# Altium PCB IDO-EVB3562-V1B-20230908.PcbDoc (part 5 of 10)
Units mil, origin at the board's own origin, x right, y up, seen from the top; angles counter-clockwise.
Board outline 5314.96 x 3543.31 mil, 4 copper layers (TOP, L2-VCC, L3-GND, BOTTOM), stack 28.8 mil thick; 747 components, 560 nets, 2514 pads, 1964 vias.
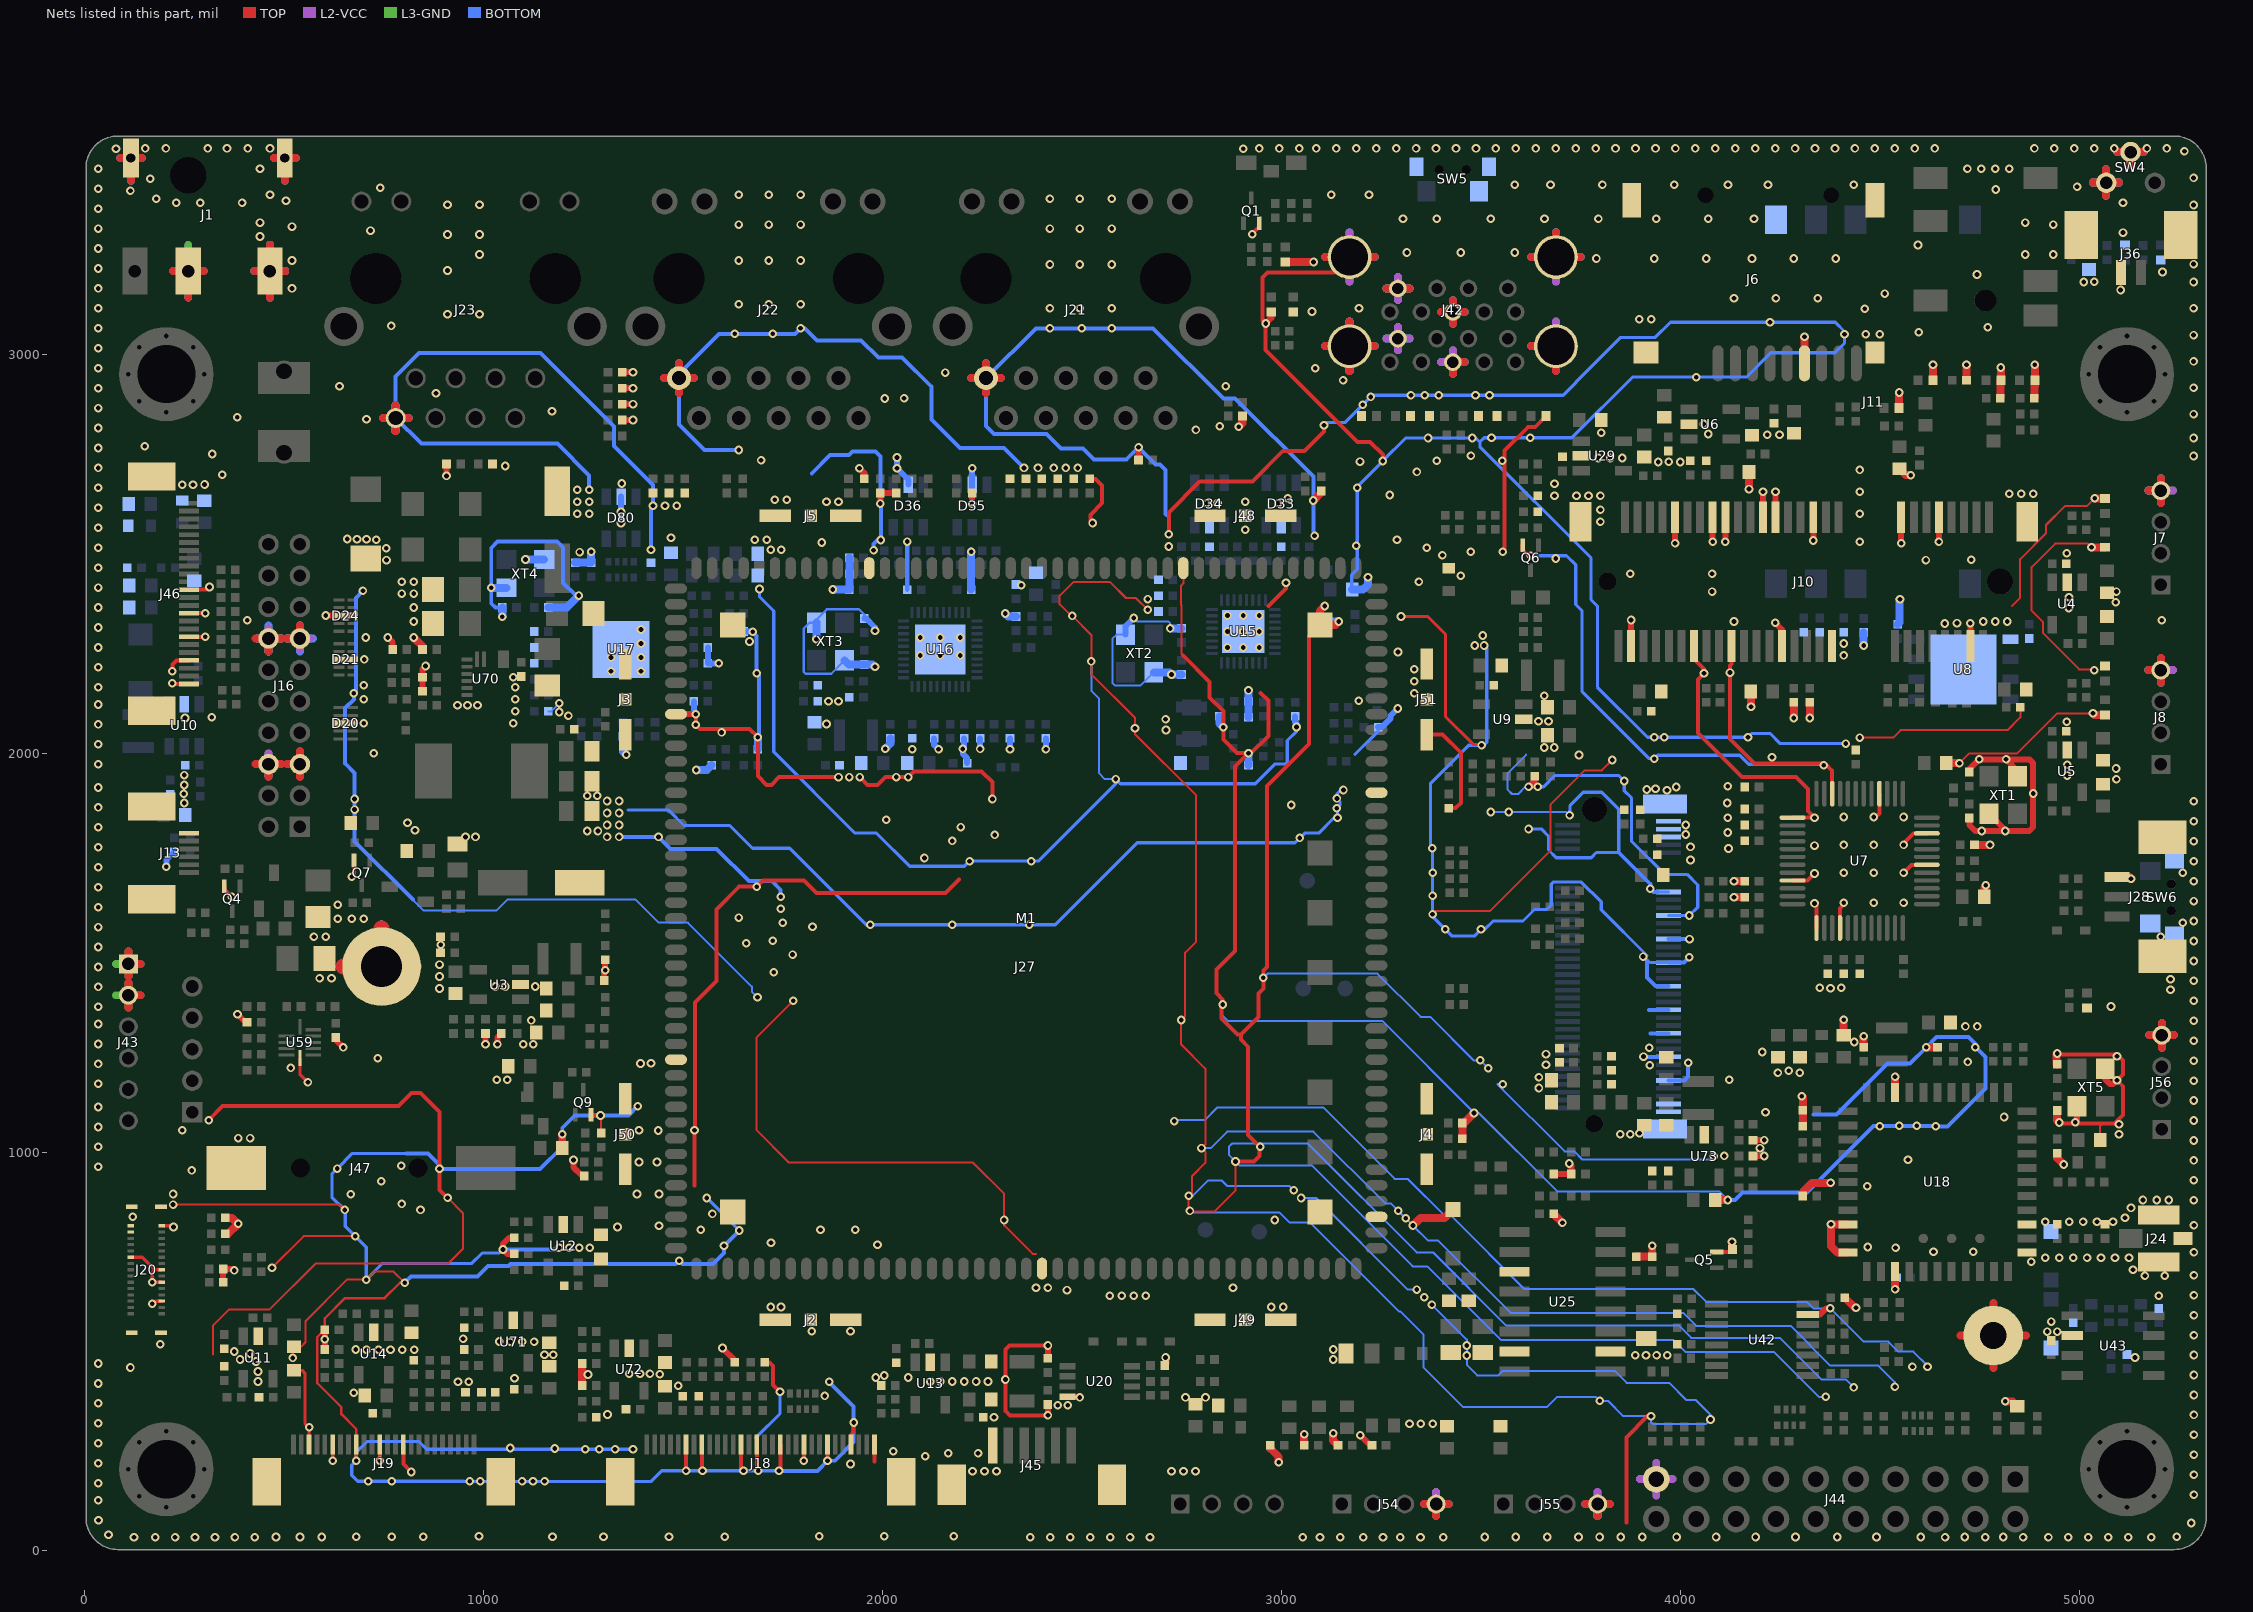
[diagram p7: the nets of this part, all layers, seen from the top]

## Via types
v1: diameter 21.65, hole 11.81, TOP to BOTTOM, 1964 vias

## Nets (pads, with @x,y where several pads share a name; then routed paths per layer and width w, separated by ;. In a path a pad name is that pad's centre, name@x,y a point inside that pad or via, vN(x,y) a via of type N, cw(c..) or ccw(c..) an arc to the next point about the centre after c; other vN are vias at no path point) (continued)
GND: C1.2 C2.1 C3.1 C28.1 C29.1 C30.1 C32.1 C33.1 C34.1 C36.1 C37.1 C39.2 C40.2 C42.2 C43.2 C45.2 C46.2 C53.1 C54.2 C61.1 C62.1 C63.1 C65.1 C67.1 C68.1 C69.1 C70.1 C74.1 C75.1 C76.1 C77.1 C80.1 C81.1 C82.1 C85.1 C86.1 C87.1 C88.1 C89.1 C90.1 C91.1 C92.1 C93.1 C94.1 C95.1 C96.1 C97.1 C98.1 C99.1 C100.1 C101.1 C102.1 C103.1 C104.1 C105.1 C107.1 C108.1 C112.2 C113.2 C114.1 C115.2 C116.2 C126.2 C128.1 C129.1 C130.1 C131.1 C132.1 C133.1 C143.1 C147.1 C150.2 C151.1 C152.1 C155.1 C156.2 C158.1 C159.1 C160.1 C163.1 C164.1 C166.1 C167.1 C168.1 C169.1 C170.1 C171.1 C176.1 C180.1 C189.1 C190.2 C191.1 C207.1 C208.1 C209.1 C210.1 C211.1 C212.1 C213.1 C214.1 C216.2 C217.2 C220.2 C221.2 C223.1 C226.1 C227.1 C261.2 C262.2 C264.1 C265.1 C266.1 C267.1 C268.1 C269.1 C270.1 C271.1 C272.1 C273.1 C274.1 C275.1 C276.1 C277.1 C278.1 C279.1 C280.1 C281.1 C282.1 C283.1 C284.2 C285.1 C287.1 C288.1 C289.1 C291.1 C292.1 C293.1 C294.1 C295.1 C301.1 C302.1 C303.1 C304.1 C305.1 C306.1 C307.2 C308.2 C309.2 C310.1 C311.1 C312.1 C313.1 C314.1 C315.1 C316.1 C318.1 C320.1 C321.1 C322.1 C323.1 C324.1 C325.1 C326.1 C327.1 C328.1 C329.1 C330.1 C331.1 C332.1 C333.1 C334.1 C335.1 C336.1 C337.1 C338.1 C339.1 C340.1 C341.1 C342.1 C343.1 C344.1 C347.1 C348.1 C349.1 C350.1 C351.1 C352.1 C355.1 C356.1 C357.1 C358.1 C359.1 C360.1 C361.1 C362.1 C363.1 C364.1 C365.1 C366.1 C367.1 C368.1 C528.2 C530.2 C531.2 C532.2 C533.2 C806.2 C807.1 C808.1 C809.1 C811.2 C812.2 C813.2 C814.2 C870.2 C871.2 C1010.1 C1011.1 C1013.1 C1014.1 C1015.1 C1016.1 C1017.1 C1018.1 C1019.1 C1020.1 C1022.1 C1023.1 C1024.1 C1025.1 C1026.1 C1027.1 C1028.1 C1029.1 C1030.1 C1031.1 C1032.1 C1033.1 C1035.1 C1036.1 C1037.1 C1038.1 C1040.1 C1041.1 C1042.1 C1044.1 C1045.1 C1046.1 C1047.1 D3.A D4.1 D5.2 D6.1 D7.2 D8.1 D9.2 D20.3 D20.8 D21.3 D21.8 D24.3 D24.8 D33.2 D34.2 D35.2 D36.2 D37.1 D38.1 D39.1 D40.1 D41.1 D42.1 D46.2 D50.2 D51.2 D65.2 D66.2 D67.2 D68.2 D69.2 D79.C D80.2 D194.C D195.C J1.2 J1.3 J1.5 J1.6 J2.1 J2.2 J2.3 J3.1 J3.2 J3.3 J4.1 J4.2 J4.3 J5.1 J5.2 J5.3 J6.6 J6.10 J6.11 J6.12 J6.13 J7.4 J8.4 J10.4 J10.9 J10.15 J10.18 J10.21 J10.26 J10.27 J10.29 J10.34 J10.35 J10.37 J10.40 J10.43 J10.50 J10.55 J10.56 J11.C5 J13.6 J13.7 J13.8 J16.5 J16.6 J16.13 J16.14 J18.1 J18.4 J18.7 J18.10 J18.13 J18.16 J18.18 J18.23 J18.25 J18.31 J18.32 J19.10 J19.13 J19.16 J19.19 J19.22 J19.25 J19.26 J20.6 J20.12 J20.16 J20.19 J20.27 J20.29 J20.30 J20.31 J20.32 J20.33 J20.34 J21.10 J22.10 J23.8 J24.1 J24.3 J24.4 J27.1 J27.3 J27.9 J27.15 J27.21 J27.27 J27.33 J27.39 J27.45 J27.51 J27.57 J27.71 J27.73 J27.75 J27.G1 J27.G2 J27.G3 J27.G4 J28.3 J28.4 J28.5 J36.2 J36.3 J36.4 J42.4 J42.7 J42.13 J42.16 J42.19 J42.20 J42.21 J42.22 J43.1 J43.2 J44.19 J45.6 J45.7 J45.8 J46.1 J46.4 J46.7 J46.10 J46.13 J46.25 J46.26 J47.2 J48.1 J48.2 J48.3 J49.1 J49.2 J49.3 J50.1 J50.2 J50.3 J51.1 J51.2 J51.3 J54.4 J55.4 J56.4 M1.3 M1.30 M1.55 M1.75 M1.95 M1.117 M1.152 M1.173 M1.180 M1.181 M1.182 M6.1 Q1.2 Q4.2 Q5.2 Q6.2 Q7.2 Q9.2 R10.1 R31.2 R34.2 R35.2 R47.2 R82.1 R133.1 R135.1 R137.1 R139.1 R158.1 R171.1 R174.1 R176.1 R179.1 R180.1 R181.1 R183.1 R184.1 R187.1 R193.2 R200.1 R209.2 R211.2 R216.2 R218.1 R220.2 R239.1 R244.1 R253.1 R306.2 R316.1 R341.2 R389.1 R412.1 R413.1 R414.2 R442.1 R446.2 R447.1 R459.2 R782.1 R785.1 R1060.2 R1067.1 R1070.1 R1169.1 R1177.2 R1178.2 R1192.2 R1198.1 R1202.2 SW4.2 SW4.3 SW5.1 SW5.2 SW5.3 SW6.1 SW6.2 SW6.3 U3.2 U4.2 U5.2 U6.2 U7.6 U7.10 U7.16 U7.22 U7.25 U7.33 U7.37 U7.40 U8.1 U8.9 U9.2 U10.2 U11.2 U12.2 U13.2 U14.2 U15.33 U16.41 U17.33 U18.1 U18.3 U18.20 U18.31 U18.33 U18.36 U20.4 U25.2 U25.11 U25.15 U29.2 U42.15 U43.2 U59.6 U70.1 U70.3 U71.2 U72.2 U73.2 XT1.2 XT1.4 XT2.2 XT2.4 XT3.2 XT3.4 XT4.2 XT4.4 XT5.2 XT5.4 | length 88813
  TOP w5: v1(222.01,868.3) 638.66,868.3 v1(651.98,854.98) ; 321.53,492.47 321.53,564.47 362.52,605.46 463.89,605.46 578.93,720.5 911.1,720.5 948.75,758.15 948.75,846.53 v1(910.14,885.14) ; v1(470,710) 549.07,789.07 v1(678.44,789.07) ; C97.1@525,512.44 543.37,512.44 553.93,523 553.93,576.39 657.54,680 v1(706,680) 726.5,700.5 774.5,700.5 v1(802.5,672.5) ; v1(1293.34,1091.67) 1295,1090.01 R1192.2@1295,1047.72 ; v1(1776.48,1379.48) 1684.82,1287.82 1684.82,1054.7 1765.64,973.89 2227.11,973.89 2305.18,895.82 v1(2305.18,829.77) 2305.18,816.4 2376.58,745 2385,745 ; v1(2665,2359.59) 2635.59,2389 2610.72,2389 2571,2428.72 2478.72,2428.72 2444.67,2394.67 2444.67,2373.13 2473.76,2344.04 v1(2475.84,2344.04) 2523.67,2296.21 v1(2523.67,2230) 2523.67,2198.18 2633.33,2088.52 v1(2633.33,2062.6) 2633.33,2047.43 2786.65,1894.11 2786.65,1527.65 2759,1500 2759,1341 v1(2749,1331) 2749,1269.7 2809.55,1209.15 2809.55,1019.55 v1(2800,1010) 2809.55,1000.45 2809.55,972.84 2776.68,939.96 2776.68,898.46 v1(2768.35,890.14) 2767.49,889.27 2767.49,855.93 v1(2770.96,852.46) 2771.97,851.45 2833.45,851.45 2885.12,903.12 v1(2885.12,976.47) ; 2753.39,2245.39 2750,2248.79 2750,2371 2749.17,2371.83 2749.17,2420.17 2754.53,2425.53 M1.55@2754.53,2463.78 ; v1(3379.33,1596.27) 3387.66,1604.59 3523.85,1604.59 3674.43,1755.17 3674.43,1871.16 3760.26,1957 3803.55,1957 v1(3829.43,1982.89) ; v1(4450,2039) 4534,2039 4552.57,2057.57 4820.51,2057.57 4852.72,2089.78 C313.1@4852.72,2114.99 ; v1(4700,1975) 4724.57,1999.57 4844.54,1999.57 4944.97,2100 v1(5035,2100) ; 4832,2369 4852.1,2389.1 4852.1,2486.1 4917,2551 4917,2572 4965,2620 5020.2,2620 v1(5039.1,2638.9) ; v1(5031,2516.1) 5022.1,2525 4940,2525 4881.1,2466.1 4881.1,2357.41 4909.81,2328.7 4909.81,2300.57 5000.38,2210 5036,2210 v1(5038,2208) ; C176.1@5052.56,1030 5052.56,1064.56 5060,1072
  TOP w6: J19.16@681.1,267.01 681.1,305.9 643.93,343.07 643.93,360.33 583.43,420.84 583.43,536.15 C268.1@602.28,555 602.28,583.02 653.26,634 752.11,634 790.61,672.5 v1(802.5,672.5)
  TOP w8: J20.19@116.03,736.49 144.96,736.49 176.45,705 ; v1(169.96,619.93) 176.29,626.26 J20.6@193.98,626.26 ; J20.12@193.98,673.5 v1(169.88,673.5) 169.88,698.43 176.45,705 ; J20.16@193.98,705 176.45,705 ; J20.30@193.98,815.23 219.77,815.23 v1(223,812) ; C96.1@525,452.56 545.44,452.56 552.43,445.57 552.43,320.56 v1(562.99,310) J19.22@562.99,267.01 ; U59.6@540,1235.63 540,1195 v1(560,1175) ; v1(622.05,226.18) J19.19@622.05,267.01 ; v1(681.1,226.18) J19.16@681.1,267.01 ; J18.4@1921.38,267.01 1921.38,292.38 1928,299 v1(1928,322) ; v1(3300,2342.48) 3367.52,2342.48 3411.75,2298.25 3411.75,2091.51 3481.19,2022.06 3500.03,2022.06 v1(3502.13,2019.96)
  TOP w10: v1(220,2175) 221.38,2173.62 J46.1@262.01,2173.62 ; v1(220,2205) 220,2222.68 230,2232.68 J46.4@262.01,2232.68 ; J46.7@262.01,2291.73 v1(302.83,2291.73) ; J46.10@262.01,2350.79 v1(302.83,2350.79) ; J46.13@262.01,2409.84 306.65,2409.84 v1(313.35,2416.54) ; v1(311.42,1080) 346.42,1115 787,1115 820,1148 842,1148 890,1100 v1(890,957.83) 890,905.28 v1(910.14,885.14) ; Q4.2@350.31,1666.5 350.31,1658.36 v1(368.68,1640) ; v1(670,1690) 675.32,1695.32 Q7.2@675.32,1731.5 ; v1(740.16,226.18) J19.13@740.16,267.01 ; J19.10@799.21,267.01 799.21,217.79 v1(819,198) ; Q9.2@1269.68,1093.5 1291.51,1093.5 v1(1293.34,1091.67) ; v1(1508,201) J18.25@1507.99,267.01 ; 1529,916 v1(1529,1055) 1530.43,1056.44 1530.43,1375.43 1583.79,1428.79 1583.79,1608.32 1640.6,1665.12 v1(1685,1665.12) 1700.73,1680.85 1803.15,1680.85 1835,1649 2158,1649 2192,1683 ; v1(1532.36,2097.64) v1(1532.36,2070.98) 1542.51,2060.83 1666.89,2060.83 v1(1687.72,2040) 1687.72,1942.39 1709.77,1920.33 1721.77,1920.33 1741.44,1940 v1(1890,1940) ; J18.23@1547.36,267.01 1547.36,202.64 v1(1549,201) ; J18.18@1645.79,267.01 1645.79,207.21 v1(1652,201) ; J18.16@1685.16,267.01 1685.16,204.84 v1(1689,201) ; R1178.2@1705,472.72 1717.28,472.72 1726.3,463.7 1726.3,416.31 v1(1743.44,399.16) ; v1(1741,201) 1744.21,204.21 J18.13@1744.21,267.01 ; v1(1803.27,226.18) J18.10@1803.27,267.01 ; v1(1862.32,226.18) J18.7@1862.32,267.01 ; v1(1943.31,1940) 1962.98,1920.33 1987.9,1920.33 2007.57,1940 v1(2035,1940) v1(2065,1940) 2079.17,1954.17 2248.86,1954.17 2275.91,1927.12 v1(2275.91,1885.03) ; 1980.43,224.57 J18.1@1980.43,267.01 ; v1(2415,340) 2320,340 2308.5,351.5 v1(2308.5,430) 2308.5,505 2318.5,515 v1(2415,515) ; C272.1@2520,2687.72 2534.28,2687.72 2551,2671 2551,2626.55 2521.42,2596.97 2521.42,2582.58 v1(2527,2577) ; v1(2718,2549) 2718,2603.27 2795.56,2680.83 2927.58,2680.83 3003.75,2757 3058,2757 3107,2806 v1(3107,2822.35) ; 2753.39,2245.39 2820.61,2178.18 2820.61,2139.39 2854.69,2105.31 v1(2854.69,2065) 2854.69,2034.1 2888.79,2000 v1(2917.72,2000) ; v1(2885.12,976.47) 2931.47,976.47 2945,990 2945,1011 v1(2947,1013) 2917,1043 2917,1264 2899,1282 2899,1295 ; v1(2927,3301) 2944.68,3318.68 Q1.2@2944.68,3328.5 ; 2948,2151 2967.48,2131.52 2967.48,2043.03 2924.45,2000 v1(2917.72,2000) ; 2967.48,2368.62 3011.79,2412.93 v1(3011.79,2426.82) ; M1.180@3096.65,2321.65 3069.14,2294.14 3069.14,2022.96 2964.15,1917.98 2964.15,1464.03 2955,1454.87 v1(2955,1436.67) 2955.83,1435.85 2955.83,1410.42 2942.5,1397.09 2942.5,1338.5 2899,1295 ; J42.21@3171.34,3243.74 3132.6,3205 2965,3205 2952.8,3192.8 2952.8,3084.96 v1(2960.75,3077) 2960.75,3010.68 3191.59,2779.85 3222.88,2779.85 3254.5,2748.23 v1(3254.5,2732.5) ; J51.2@3365,2046.42 3404.58,2046.42 3450,2001 3450,1875 3437.28,1862.28 C271.1@3419.99,1862.28 ; v1(3555,2505) 3560,2510 3560,2758.67 3618.33,2817 3635.9,2817 D39.1@3663.9,2845 ; Q6.2@3605.32,2521.5 3605.32,2509.68 3620,2495 v1(3625,2495) ; 3865,71 3865,284.43 3918.6,338.02 v1(3926.84,338.02) ; J10.40@4034.4,2268.6 4034.4,2235.95 4059.82,2210.53 v1(4059.82,2200.01) 4044.15,2184.34 4044.15,2050.85 4155,1940 4290,1940 4320,1910 4320,1855 v1(4336.7,1838.3) U7.25@4281.7,1838.3 ; Q5.2@4091.5,749.68 4124.97,749.68 R446.2@4131,755.72 ; J10.34@4128.9,2268.6 4128.9,2223.9 4125,2220 v1(4125,2202) 4125,2035 4186,1974 4356,1974 v1(4360,1970) 4367,1970 4381.1,1955.9 U7.22@4381.1,1898.3 ; U7.33@4281.7,1680.8 4319.2,1680.8 v1(4336.7,1698.3) ; v1(4336.7,1623.3) 4341.7,1618.3 U7.37@4341.7,1561.7 ; U7.40@4400.8,1561.7 4400.8,1610.8 4410,1620 v1(4410,1625) ; v1(4485,1840) 4490,1840 4499.2,1849.2 U7.16@4499.2,1898.3 ; v1(4560,1700) 4580.2,1720.2 U7.6@4618.3,1720.2 ; v1(4560,1770) 4560,1773.9 4585,1798.9 U7.10@4618.3,1798.9 ; v1(4945,1247) 4947.12,1244.88 5094.41,1244.88 5110,1229.29 5110,1195 v1(5095,1180) 5110,1165 5110,1093 5089,1072 5060,1072 4995,1072 4952,1072 v1(4950,1074) ; 2899,1295 2890,1295 2850.32,1334.67 2850.32,1367.21 v1(2853.11,1370) 2853.11,1382.56 2837.3,1398.37 2837.3,1457.21 2884.15,1504.06 2884.15,1966.43 v1(2917.72,2000)
  TOP w15: C1028.1@347.72,673.99 C288.1@347.72,707 371.36,707 v1(375,703.36) ; v1(383.36,1345.22) 403.58,1325 C285.1@407.28,1325 ; R139.1@602.28,505 v1(602.28,530.72) C268.1@602.28,555 ; v1(605,2345) D24.3@639.44,2345 D24.8@670.56,2345 ; C284.2@630.01,1287.28 630.01,1280.89 v1(648.56,1262.34) ; v1(760,2290) 772.28,2277.72 R1060.2@772.28,2260 ; R782.1@847.28,2155 R785.1@847.28,2190 847.28,2210.6 v1(855,2218.32) ; v1(907.28,2695) C166.1@907.28,2725 ; v1(1005,1270) R10.1@1005,1297.28 ; v1(1035,1270) 1035,1287.28 C37.1@1045,1297.28 ; R135.1@1077.28,745 1059.91,745 v1(1049,755.91) 1049,770 1064,785 C266.1@1077.28,785 ; v1(1225.6,980) 1225.6,962.3 1247.89,940.01 C269.1@1252.28,940.01 ; C36.1@1302.72,1429.99 1302.72,1453.33 v1(1304.99,1455.6) C95.1@1304.99,1482.28 ; C152.1@1347.72,2834.99 v1(1375,2834.99) ; R200.1@1347.72,2875 v1(1375,2875) ; C150.2@1347.72,2915.01 v1(1375,2915.01) ; R218.1@1347.72,2955 v1(1375,2955) ; M1.95@1482.87,2097.64 v1(1532.36,2097.64) ; v1(1599.33,508.67) 1630.01,477.99 C94.1@1630.01,472.72 ; v1(1942.48,2714.31) 1955,2701.8 C270.1@1955,2687.72 ; v1(1994.99,2625.6) C147.1@1994.99,2652.28 C131.1@2035,2652.28 ; v1(2225,2625.6) C112.2@2225,2652.28 ; v1(2415,340) C191.1@2415,367.28 ; C189.1@2415,482.72 v1(2415,515) ; U20.4@2464.29,386.62 2493.38,386.62 v1(2495,385) ; C114.1@2642.28,2735.01 v1(2642.28,2766.68) ; C190.2@2707.72,465.01 2712.72,470.01 2712.72,482.28 v1(2710,485) ; v1(2960.75,3077) 2975,3091.25 D37.1@2975,3106.1 ; v1(3198.3,289.92) 3223.22,265 C217.2@3227.28,265 ; v1(3620,1915.6) 3635,1930.6 R442.1@3635,1942.28 ; R306.2@3682.72,945 C214.1@3727.28,945.01 3727.28,966.02 v1(3721.84,971.47) ; J10.50@3876.9,2268.6 v1(3876.9,2333.8) ; v1(3987.2,2526.2) J10.43@3987.2,2591.4 ; v1(4081.6,2530.2) J10.37@4081.6,2591.4 ; v1(4113.2,2530.2) J10.35@4113.2,2591.4 ; R1169.1@4182.72,990 v1(4211,990) ; C1045.1@4182.72,1030 v1(4211,1030) ; J10.29@4207.6,2591.4 v1(4207.6,2655) ; v1(4238,2327) 4254.9,2310.1 J10.26@4254.9,2268.6 ; J10.27@4239.1,2591.4 v1(4239.1,2655) ; U42.15@4319.7,593.14 4351.14,593.14 4366.31,608.32 v1(4376.35,608.32) ; v1(4333.6,2533) J10.21@4333.6,2591.4 ; v1(4554.1,2526.2) J10.15@4554.1,2591.4 ; v1(4648.6,2530) J10.9@4648.6,2591.4 ; C53.1@4725,1837.28 4725,1820 4740,1805 v1(4756,1805) v1(4815,1805) ; C54.2@4725,1952.72 4725,1959.57 v1(4750,1984.57) v1(4817,1984.57) ; J10.4@4727.3,2268.6 v1(4727.3,2325.8) ; XT1.4@4774.57,1847.76 4815,1807.32 v1(4815,1805) ; XT1.2@4845.43,1942.24 4845.43,1956.13 v1(4817,1984.57) ; XT5.2@4994.57,1114.76 4994.57,1072.43 v1@4995,1072 ; XT5.4@5065.43,1209.24 5065.43,1182.57 5078,1170 5085,1170 v1(5095,1180) ; v1(4815,1805) 4875,1805 4885,1815 v1(4885,1899) 4885,1975 4875.43,1984.57 v1(4817,1984.57)
  TOP w20: 89.61,3491.9 J1.6@116.3,3491.9 ; 110,1362.49 J43.2@110,1393.11 ; 110,1423.73 J43.2@110,1393.11 ; 110,1441.23 J43.1@110,1471.85 ; 110,1502.47 J43.1@110,1471.85 ; 116.3,3435.69 J1.6@116.3,3491.9 ; 140.62,1393.11 J43.2@110,1393.11 ; 140.62,1471.85 J43.1@110,1471.85 ; 142.99,3491.9 J1.6@116.3,3491.9 ; 221.5,3208.4 J1.3@260,3208.4 ; 260,3142.34 J1.3@260,3208.4 ; 298.5,3208.4 J1.3@260,3208.4 ; C1030.1@352.72,794.99 359.99,794.99 v1(385,820) 370.01,834.99 C1029.1@352.72,834.99 ; 426.2,3208.4 J1.2@464.7,3208.4 ; 428.67,1972.48 J16.6@461.26,1972.48 ; 428.67,2287.44 J16.14@461.26,2287.44 ; 461.26,1939.89 J16.6@461.26,1972.48 ; 461.26,2254.85 J16.14@461.26,2287.44 ; 464.7,3142.34 J1.2@464.7,3208.4 ; 464.7,3274.46 J1.2@464.7,3208.4 ; 475.41,3491.9 J1.5@502.1,3491.9 ; 493.85,1972.48 J16.6@461.26,1972.48 ; 493.85,2287.44 J16.14@461.26,2287.44 ; 502.1,3435.69 J1.5@502.1,3491.9 ; 503.2,3208.4 J1.2@464.7,3208.4 ; 507.41,1972.48 J16.5@540,1972.48 ; 507.41,2287.44 J16.13@540,2287.44 540,2320.03 ; 528.78,3491.9 J1.5@502.1,3491.9 ; 540,1939.89 J16.5@540,1972.48 ; 540,2005.07 J16.5@540,1972.48 ; 748,2840 J23.8@780,2840 ; 780,2808 J23.8@780,2840 ; 780,2872 J23.8@780,2840 ; 812,2840 J23.8@780,2840 ; v1(825,2290) 847.28,2267.72 C814.2@847.28,2260 ; C1033.1@1197.56,1010 v1(1197.56,1045) ; R1070.1@1247.28,415 1247.28,441.28 1248.28,442.28 ; C1018.1@1247.28,470 1247.28,443.28 1248.28,442.28 ; v1(1262.28,442.28) 1248.28,442.28 ; 1453,2940 J22.10@1490,2940 ; 1490,2903 J22.10@1490,2940 ; 1490,2977 J22.10@1490,2940 ; 1527,2940 J22.10@1490,2940 ; 2223,2940 J21.10@2260,2940 ; 2260,2903 J21.10@2260,2940 ; 2260,2977 J21.10@2260,2940 ; 2297,2940 J21.10@2260,2940 ; v1(2893.2,2818.33) 2902.72,2827.85 C113.2@2902.72,2845.01 ; C221.2@2972.28,265 2972.28,257.38 2993.53,236.12 v1(2993.53,222.17) ; D46.2@3010,3231.1 v1(3081,3231.1) ; C220.2@3057.28,265 v1(3057.28,292.28) ; v1(3080.48,2633.19) 3100,2652.71 C279.1@3100,2657.28 ; v1(3108.78,2368.98) 3096.65,2356.85 M1.180@3096.65,2321.65 3135.63,2321.65 v1(3143.98,2330) ; 3109.34,3020.12 J42.20@3171.34,3020.12 ; 3109.34,3243.74 J42.21@3171.34,3243.74 3233.34,3243.74 ; v1(3130,295) 3130,277.28 C216.2@3142.28,265 ; 3171.34,2958.12 J42.20@3171.34,3020.12 ; 3171.34,3082.12 J42.20@3171.34,3020.12 ; 3233.34,3020.12 J42.20@3171.34,3020.12 ; 3263.2,3165 J42.4@3292.2,3165 3321.2,3165 ; v1(3329.96,815.96) 3348.86,834.86 3408.84,834.86 D79.C@3430,856.02 ; 3357.49,117.72 J54.4@3388.11,117.72 ; 3388.11,87.09 J54.4@3388.11,117.72 ; 3401,3105.94 J42.7@3430,3105.94 ; 3418.73,117.72 J54.4@3388.11,117.72 ; 3430,2950.96 J42.16@3430,2979.96 3459,2979.96 ; 3430,3076.94 J42.7@3430,3105.94 ; 3430,3134.94 J42.7@3430,3105.94 ; C302.1@3453.72,1033 R389.1@3453.72,1073 3458.18,1073 v1(3483.18,1098) ; 3459,3105.94 J42.7@3430,3105.94 ; 3626.66,3020.12 J42.19@3688.66,3020.12 3688.66,2958.12 ; 3626.66,3243.74 J42.22@3688.66,3243.74 ; C209.1@3682.72,844.99 v1(3704.76,822.95) ; 3688.66,3305.74 J42.22@3688.66,3243.74 ; 3750.66,3243.74 J42.22@3688.66,3243.74 ; 3762.49,117.72 J55.4@3793.11,117.72 ; 3793.11,87.09 J55.4@3793.11,117.72 ; 3823.73,117.72 J55.4@3793.11,117.72 ; C208.1@3890,737.71 C207.1@3930,737.72 v1(3930,765) ; C1037.1@4087.56,880 v1(4119.14,880) ; v1(4130,775) 4130,756.72 R446.2@4131,755.72 ; v1(4135,1639) C311.1@4162.28,1639 ; v1(4135,1679) C306.1@4162.28,1679 ; v1(4172.56,2662) C67.1@4172.56,2705 ; v1(4177.44,2116) C69.1@4177.44,2155 ; v1(4285,2088.28) C76.1@4285,2127.28 ; v1(4305,1140) 4307.28,1137.72 C343.1@4307.28,1105 C180.1@4307.28,1065 ; R244.1@4307.28,890 4307.28,900.28 4330,923 v1(4377,923) ; J6.6@4311.54,2977.13 v1(4311.54,3043.54) ; v1(4325,2088.28) C1035.1@4325,2127.28 ; v1(4378,818.7) 4377.97,764.03 4394.17,747.83 U18.33@4420.59,747.83 ; v1(4378,818.7) U18.31@4420.59,818.7 ; C366.1@4410,1292.56 v1(4410,1332) ; C1036.1@4412.72,634.99 4437.71,610 v1(4440.65,610) ; C342.1@4460,1262.72 v1(4460,1290) ; v1(4538.7,656.3) U18.36@4538.7,700.59 ; U18.20@4538.7,1149.41 v1(4538.7,1189) ; D69.2@4548.9,2865 v1(4548.9,2904) ; C280.1@4550,2712.44 4565.44,2697 v1(4578,2697) ; v1(4617,1262.72) C170.1@4645,1262.72 ; D68.2@4633.9,2935 v1(4633.9,2974) ; C356.1@4666.56,1975 v1(4700,1975) ; 4703.19,540 M6.1@4785,540 ; R316.1@4717.72,2935 v1(4717.72,2974) ; C303.1@4737.72,1770 v1(4776.72,1770) ; C355.1@4762.56,1640 4762.56,1661.56 4766,1665 4766,1666 4766.79,1666.79 4766.79,1668.21 v1(4766,1669) ; 4785,458.19 M6.1@4785,540 ; 4785,621.8 M6.1@4785,540 ; R447.1@4802.72,2890 4802.72,2933.82 D66.2@4803.9,2935 v1(4803.9,2966.9) ; v1(4815,375) 4832.56,375 C264.1@4845,362.56 ; 4866.81,540 M6.1@4785,540 ; C223.1@4887.72,2890 4887.72,2918.72 4888.9,2919.9 D67.2@4888.9,2935 v1(4888.9,2974) ; C344.1@4945,997.28 4945,985.47 v1(4961.47,969) ; C167.1@4945,1104.28 4945,1079 v1(4950,1074) ; C171.1@4945,1219.72 4943.59,1221.13 4943.59,1245.59 v1(4945,1247) ; v1(5031,2516.1) D4.1@5065,2516.1 ; v1(5035,2100) 5038.9,2096.1 D6.1@5065,2096.1 ; 5035.36,3430 SW4.2@5067.95,3430 ; v1(5039.1,2638.9) D5.2@5065,2638.9 ; 5067.95,3397.41 SW4.2@5067.95,3430 ; 5067.95,3462.59 SW4.2@5067.95,3430 ; J28.3@5095,1689.21 5125.79,1689.21 v1(5130,1685) ; 5096.38,3506.77 SW4.3@5128.98,3506.77 ; 5100.55,3430 SW4.2@5067.95,3430 ; 5128.98,3474.18 SW4.3@5128.98,3506.77 ; 5161.57,3506.77 SW4.3@5128.98,3506.77 ; 5174.38,2208.11 J8.4@5205,2208.11 ; 5174.38,2658.11 J7.4@5205,2658.11 ; 5176.66,1293.11 J56.4@5207.28,1293.11 ; 5205,2177.49 J8.4@5205,2208.11 ; 5205,2238.73 J8.4@5205,2208.11 ; 5205,2627.49 J7.4@5205,2658.11 ; 5205,2688.73 J7.4@5205,2658.11 ; 5207.28,1262.49 J56.4@5207.28,1293.11 ; 5207.28,1323.73 J56.4@5207.28,1293.11 ; 5237.91,1293.11 J56.4@5207.28,1293.11
  TOP w40: J27.G3@649.1,1465 J27.G4@744.68,1465 J27.G3@744.68,1560.59
  L2-VCC w20: 89.61,3491.9 J1.6@116.3,3491.9 ; 116.3,3435.69 J1.6@116.3,3491.9 ; 142.99,3491.9 J1.6@116.3,3491.9 ; 426.2,3208.4 J1.2@464.7,3208.4 ; 434.57,1972.48 J16.6@461.26,1972.48 ; 434.57,2287.44 J16.14@461.26,2287.44 ; 461.26,1945.79 J16.6@461.26,1972.48 ; 461.26,1999.17 J16.6@461.26,1972.48 ; 461.26,2260.75 J16.14@461.26,2287.44 ; 461.26,2314.13 J16.14@461.26,2287.44 ; 464.7,3142.34 J1.2@464.7,3208.4 ; 464.7,3274.46 J1.2@464.7,3208.4 ; 475.41,3491.9 J1.5@502.1,3491.9 ; 487.95,1972.48 J16.6@461.26,1972.48 ; 487.95,2287.44 J16.14@461.26,2287.44 ; 502.1,3435.69 J1.5@502.1,3491.9 ; 503.2,3208.4 J1.2@464.7,3208.4 ; 513.31,1972.48 J16.5@540,1972.48 ; 513.31,2287.44 J16.13@540,2287.44 ; 528.78,3491.9 J1.5@502.1,3491.9 ; 540,1945.79 J16.5@540,1972.48 ; 540,1999.17 J16.5@540,1972.48 ; 540,2260.75 J16.13@540,2287.44 ; 540,2314.13 J16.13@540,2287.44 ; 566.69,2287.44 J16.13@540,2287.44 ; 748,2840 J23.8@780,2840 ; 780,2808 J23.8@780,2840 ; 780,2872 J23.8@780,2840 ; 812,2840 J23.8@780,2840 ; 1453,2940 J22.10@1490,2940 ; 1490,2903 J22.10@1490,2940 ; 1490,2977 J22.10@1490,2940 ; 1527,2940 J22.10@1490,2940 ; 2223,2940 J21.10@2260,2940 ; 2260,2903 J21.10@2260,2940 ; 2260,2977 J21.10@2260,2940 ; 2297,2940 J21.10@2260,2940 ; 3109.34,3020.12 J42.20@3171.34,3020.12 ; 3109.34,3243.74 J42.21@3171.34,3243.74 ; 3171.34,2958.12 J42.20@3171.34,3020.12 ; 3171.34,3082.12 J42.20@3171.34,3020.12 ; 3171.34,3181.74 J42.21@3171.34,3243.74 ; 3171.34,3305.74 J42.21@3171.34,3243.74 ; 3233.34,3020.12 J42.20@3171.34,3020.12 ; 3233.34,3243.74 J42.21@3171.34,3243.74 ; 3263.2,3039.02 J42.13@3292.2,3039.02 ; 3263.2,3165 J42.4@3292.2,3165 ; 3292.2,3010.02 J42.13@3292.2,3039.02 ; 3292.2,3068.02 J42.13@3292.2,3039.02 ; 3292.2,3136 J42.4@3292.2,3165 ; 3292.2,3194 J42.4@3292.2,3165 ; 3321.2,3039.02 J42.13@3292.2,3039.02 ; 3321.2,3165 J42.4@3292.2,3165 ; 3357.49,117.72 J54.4@3388.11,117.72 ; 3388.11,87.09 J54.4@3388.11,117.72 ; 3388.11,148.34 J54.4@3388.11,117.72 ; 3401,2979.96 J42.16@3430,2979.96 ; 3401,3105.94 J42.7@3430,3105.94 ; 3418.73,117.72 J54.4@3388.11,117.72 ; 3430,2950.96 J42.16@3430,2979.96 ; 3430,3008.96 J42.16@3430,2979.96 ; 3430,3076.94 J42.7@3430,3105.94 ; 3430,3134.94 J42.7@3430,3105.94 ; 3459,2979.96 J42.16@3430,2979.96 ; 3459,3105.94 J42.7@3430,3105.94 ; 3626.66,3020.12 J42.19@3688.66,3020.12 ; 3626.66,3243.74 J42.22@3688.66,3243.74 ; 3688.66,2958.12 J42.19@3688.66,3020.12 ; 3688.66,3082.12 J42.19@3688.66,3020.12 ; 3688.66,3181.74 J42.22@3688.66,3243.74 ; 3688.66,3305.74 J42.22@3688.66,3243.74 ; 3750.66,3243.74 J42.22@3688.66,3243.74 ; 3762.49,117.72 J55.4@3793.11,117.72 ; 3793.11,87.09 J55.4@3793.11,117.72 ; 3793.11,148.34 J55.4@3793.11,117.72 ; 3823.73,117.72 J55.4@3793.11,117.72 ; 3899.53,180 J44.19@3940,180 ; 3940,139.53 J44.19@3940,180 ; 3940,220.47 J44.19@3940,180 ; 3980.47,180 J44.19@3940,180 ; 4728.78,540 M6.1@4785,540 ; 4785,483.79 M6.1@4785,540 ; 4785,596.22 M6.1@4785,540 ; 4841.22,540 M6.1@4785,540 ; 5035.36,3430 SW4.2@5067.95,3430 ; 5067.95,3397.41 SW4.2@5067.95,3430 ; 5067.95,3462.59 SW4.2@5067.95,3430 ; 5096.38,3506.77 SW4.3@5128.98,3506.77 ; 5100.55,3430 SW4.2@5067.95,3430 ; 5128.98,3474.18 SW4.3@5128.98,3506.77 ; 5161.57,3506.77 SW4.3@5128.98,3506.77 ; 5174.38,2208.11 J8.4@5205,2208.11 ; 5174.38,2658.11 J7.4@5205,2658.11 ; 5176.66,1293.11 J56.4@5207.28,1293.11 ; 5205,2177.49 J8.4@5205,2208.11 ; 5205,2238.73 J8.4@5205,2208.11 ; 5205,2627.49 J7.4@5205,2658.11 ; 5205,2688.73 J7.4@5205,2658.11 ; 5207.28,1262.49 J56.4@5207.28,1293.11 ; 5207.28,1323.73 J56.4@5207.28,1293.11 ; 5235.62,2208.11 J8.4@5205,2208.11 ; 5235.62,2658.11 J7.4@5205,2658.11 ; 5237.91,1293.11 J56.4@5207.28,1293.11
  L2-VCC w40: 668.78,1465 J27.G4@744.68,1465 ; 744.68,1389.1 J27.G4@744.68,1465 ; 744.68,1540.9 J27.G4@744.68,1465 ; 825,1465 J27.G4@744.68,1465
  L3-GND w20: 79.38,1393.11 J43.2@110,1393.11 ; 79.38,1471.85 J43.1@110,1471.85 ; 89.61,3491.9 J1.6@116.3,3491.9 ; 110,1362.49 J43.2@110,1393.11 ; 110,1423.73 J43.2@110,1393.11 ; 110,1441.23 J43.1@110,1471.85 ; 110,1502.47 J43.1@110,1471.85 ; 116.3,3435.69 J1.6@116.3,3491.9 ; 140.62,1393.11 J43.2@110,1393.11 ; 140.62,1471.85 J43.1@110,1471.85 ; 142.99,3491.9 J1.6@116.3,3491.9 ; 221.5,3208.4 J1.3@260,3208.4 ; 260,3142.34 J1.3@260,3208.4 ; 260,3274.46 J1.3@260,3208.4 ; 298.5,3208.4 J1.3@260,3208.4 ; 426.2,3208.4 J1.2@464.7,3208.4 ; 434.57,1972.48 J16.6@461.26,1972.48 ; 434.57,2287.44 J16.14@461.26,2287.44 ; 461.26,1945.79 J16.6@461.26,1972.48 ; 461.26,1999.17 J16.6@461.26,1972.48 ; 461.26,2260.75 J16.14@461.26,2287.44 ; 461.26,2314.13 J16.14@461.26,2287.44 ; 464.7,3142.34 J1.2@464.7,3208.4 ; 464.7,3274.46 J1.2@464.7,3208.4 ; 475.41,3491.9 J1.5@502.1,3491.9 ; 487.95,1972.48 J16.6@461.26,1972.48 ; 487.95,2287.44 J16.14@461.26,2287.44 ; 502.1,3435.69 J1.5@502.1,3491.9 ; 503.2,3208.4 J1.2@464.7,3208.4 ; 513.31,1972.48 J16.5@540,1972.48 ; 513.31,2287.44 J16.13@540,2287.44 ; 528.78,3491.9 J1.5@502.1,3491.9 ; 540,1945.79 J16.5@540,1972.48 ; 540,1999.17 J16.5@540,1972.48 ; 540,2260.75 J16.13@540,2287.44 ; 540,2314.13 J16.13@540,2287.44 ; 566.69,2287.44 J16.13@540,2287.44 ; 668.78,1465 J27.G4@744.68,1465 ; 744.68,1389.1 J27.G4@744.68,1465 ; 744.68,1540.9 J27.G4@744.68,1465 ; 748,2840 J23.8@780,2840 ; 780,2808 J23.8@780,2840 ; 780,2872 J23.8@780,2840 ; 812,2840 J23.8@780,2840 ; 820.59,1465 J27.G4@744.68,1465 ; 1453,2940 J22.10@1490,2940 ; 1490,2903 J22.10@1490,2940 ; 1490,2977 J22.10@1490,2940 ; 1527,2940 J22.10@1490,2940 ; 2223,2940 J21.10@2260,2940 ; 2260,2903 J21.10@2260,2940 ; 2260,2977 J21.10@2260,2940 ; 2297,2940 J21.10@2260,2940 ; 3109.34,3020.12 J42.20@3171.34,3020.12 ; 3109.34,3243.74 J42.21@3171.34,3243.74 ; 3171.34,2958.12 J42.20@3171.34,3020.12 ; 3171.34,3082.12 J42.20@3171.34,3020.12 ; 3171.34,3181.74 J42.21@3171.34,3243.74 ; 3171.34,3305.74 J42.21@3171.34,3243.74 ; 3233.34,3020.12 J42.20@3171.34,3020.12 ; 3233.34,3243.74 J42.21@3171.34,3243.74 ; 3263.2,3039.02 J42.13@3292.2,3039.02 ; 3263.2,3165 J42.4@3292.2,3165 ; 3292.2,3010.02 J42.13@3292.2,3039.02 ; 3292.2,3068.02 J42.13@3292.2,3039.02 ; 3292.2,3136 J42.4@3292.2,3165 ; 3292.2,3194 J42.4@3292.2,3165 ; 3321.2,3039.02 J42.13@3292.2,3039.02 ; 3321.2,3165 J42.4@3292.2,3165 ; 3357.49,117.72 J54.4@3388.11,117.72 ; 3388.11,87.09 J54.4@3388.11,117.72 ; 3388.11,148.34 J54.4@3388.11,117.72 ; 3401,2979.96 J42.16@3430,2979.96 ; 3401,3105.94 J42.7@3430,3105.94 ; 3418.73,117.72 J54.4@3388.11,117.72 ; 3430,2950.96 J42.16@3430,2979.96 ; 3430,3008.96 J42.16@3430,2979.96 ; 3430,3076.94 J42.7@3430,3105.94 ; 3430,3134.94 J42.7@3430,3105.94 ; 3459,2979.96 J42.16@3430,2979.96 ; 3459,3105.94 J42.7@3430,3105.94 ; 3626.66,3020.12 J42.19@3688.66,3020.12 ; 3626.66,3243.74 J42.22@3688.66,3243.74 ; 3688.66,2958.12 J42.19@3688.66,3020.12 ; 3688.66,3082.12 J42.19@3688.66,3020.12 ; 3688.66,3181.74 J42.22@3688.66,3243.74 ; 3688.66,3305.74 J42.22@3688.66,3243.74 ; 3750.66,3243.74 J42.22@3688.66,3243.74 ; 3762.49,117.72 J55.4@3793.11,117.72 ; 3793.11,87.09 J55.4@3793.11,117.72 ; 3793.11,148.34 J55.4@3793.11,117.72 ; 3823.73,117.72 J55.4@3793.11,117.72 ; 3899.53,180 J44.19@3940,180 ; 3940,139.53 J44.19@3940,180 ; 3940,220.47 J44.19@3940,180 ; 3980.47,180 J44.19@3940,180 ; 4728.78,540 M6.1@4785,540 ; 4785,483.79 M6.1@4785,540 ; 4785,596.22 M6.1@4785,540 ; 4841.22,540 M6.1@4785,540 ; 5035.36,3430 SW4.2@5067.95,3430 ; 5067.95,3397.41 SW4.2@5067.95,3430 ; 5067.95,3462.59 SW4.2@5067.95,3430 ; 5096.38,3506.77 SW4.3@5128.98,3506.77 ; 5100.55,3430 SW4.2@5067.95,3430 ; 5128.98,3474.18 SW4.3@5128.98,3506.77 ; 5161.57,3506.77 SW4.3@5128.98,3506.77 ; 5174.38,2208.11 J8.4@5205,2208.11 ; 5174.38,2658.11 J7.4@5205,2658.11 ; 5176.66,1293.11 J56.4@5207.28,1293.11 ; 5205,2177.49 J8.4@5205,2208.11 ; 5205,2238.73 J8.4@5205,2208.11 ; 5205,2627.49 J7.4@5205,2658.11 ; 5205,2688.73 J7.4@5205,2658.11 ; 5207.28,1262.49 J56.4@5207.28,1293.11 ; 5207.28,1323.73 J56.4@5207.28,1293.11 ; 5235.62,2208.11 J8.4@5205,2208.11 ; 5235.62,2658.11 J7.4@5205,2658.11 ; 5237.91,1293.11 J56.4@5207.28,1293.11
  BOTTOM w5: 823,1633 850.89,1605.11 1032.32,1605.11 1060.22,1633 1381.39,1633 1439.39,1575 1512.36,1575 1672.63,1414.73 1672.63,1402.37 v1(1687.17,1387.83) ; R1198.1@1162.72,2105 1170,2105 v1(1190,2125) ; v1(2523.67,2230) 2523.67,2156.43 2542.5,2137.6 2542.5,1950.5 2558,1935 v1(2585,1935) ; XT2.4@2609.57,2297.24 2587.24,2297.24 2577.5,2287.5 2577.5,2175 2583.5,2169 2646.68,2169 XT2.2@2680.43,2202.76 ; v1(2630,2338.66) 2638.33,2330.34 2716.66,2330.34 2721.67,2325.33 v1(2721.67,2312.72) ; v1(2732.07,1077.67) 2732.07,1077.93 2734.41,1080.26 2808.34,1080.26 2840.14,1112.07 3104.93,1112.07 3284.28,932.72 3316.43,932.72 3410.58,838.57 3427.75,838.57 3430.66,835.66 3609.65,656.67 4032.48,656.67 4064.8,624.35 4317.59,624.35 4333.62,608.32 v1(4376.35,608.32) 4460,524.67 4521.9,524.67 4547.01,499.57 4584.7,499.57 4620,464.27 v1(4620,461.9) ; v1(2768.35,890.14) 2778.59,890.14 2817.34,928.88 2850.22,928.88 2864.1,915 3020.1,915 v1(3031.09,904.01) ; v1(2770.96,852.46) 2775.42,848 2996.18,848 3021.18,823 3073,823 3296,600 3299.29,600 3301.77,597.52 3356.33,542.96 3356.33,460.67 3456.67,360.33 3665.65,360.33 3691.62,386.3 3788.56,386.3 v1(3798.51,376.35) 3819.05,376.35 3857.37,338.02 v1(3926.84,338.02) 3926.84,323.16 3932,318 4064.21,318 v1(4075.93,329.72) 4075.93,341.5 4039.01,378.42 4015.15,378.42 3972.21,421.35 3865.98,421.35 3836.03,451.3 3555.3,451.3 3544.33,440.33 3491,440.33 3465,466.33 v1(3465,490) v1(3465,515) 3465,530 3464.86,530 v1(3377.6,617.26) ; v1(2800,1010) 2822.93,1010 2864.37,1051.44 3080.7,1051.44 3261.43,870.72 3275.33,870.72 v1@3292.89,853.15 ; v1(2853.11,1370) 2850.32,1367.21 2850.32,1344.67 2865.93,1329.07 3252.99,1329.07 3483.18,1098.88 v1(3483.18,1098) 3494.95,1098 3691.56,901.4 4097.74,901.4 v1(4119.14,880) ; v1(2955,1436.67) 2965.51,1447.18 3240.95,1447.18 3349.14,1339 3372.94,1339 3481.94,1230 v1(3499,1230) v1(3518.57,1210.42) 3521.67,1207.33 v1@3521.67,1202.41 ; v1(3049.71,884.93) 3087.07,884.93 3316.76,655.25 v1(3339.65,655.25) ; v1(3292.89,853.11) 3297.78,853.11 3298.78,852.11 3298.78,847.22 v1(3311.74,834.26) v1(3329.96,815.96) v1(3329.96,815.96) 3367.34,778.57 3392.82,778.57 3574.72,596.67 4007.62,596.67 4039.95,564.35 4276.65,564.35 4376.33,464.67 4497.04,464.67 4538.25,423.46 v1(4538.25,411.69) ; v1(3525.33,1852.56) v1(3570.5,1852.56) 3714.68,1852.56 v1(3722.76,1844.49) ; v1@3555,1174 v1(3555,1170) v1(3555,1170) 3541.89,1170.05 3710.44,1001.5 3733.99,1001.5 3754.09,981.4 4075.4,981.4 v1(4083.72,989.73) ; 3614.05,1996 3567.6,1949.56 3567.6,1908.34 3578.34,1897.61 3593.53,1897.61 3611.52,1915.6 v1(3620,1915.6) ; v1(4365,386.52) 4347.74,386.52 4234.92,499.35 4013.02,499.35 3983.15,529.22 3550.25,529.22 3365.89,713.57 3329.43,713.57 3077.15,965.85 2895.74,965.85 v1(2885.12,976.47) 2869.55,992.04 2869.55,1014.19 2876.8,1021.44 3066.27,1021.44 3339.14,748.57 3380.39,748.57 3564.22,564.75 3997.12,564.75 4027.52,534.35 4249.42,534.35 4353.77,430 4415,430 v1(4435,410)
  BOTTOM w6: XT3.2@1905.43,2232.76 1871.84,2199.16 1807.63,2199.16 1802.94,2203.85 1802.94,2312.32 1817.87,2327.24 XT3.4@1834.57,2327.24 1834.57,2334.57 1860.83,2360.84 1941.16,2360.84 1955,2347 C128.1@1955,2337.72
  BOTTOM w8: 807.71,996.6 671.48,996.6 v1(633.44,958.56) 620,945.12 620,886.96 v1(651.98,854.98) 653.48,853.48 653.48,814.03 v1(678.44,789.07) 706,761.51 v1(706,680) 746.85,720.85 971.13,720.85 997.29,747 1040.09,747 v1(1049,755.91) ; 1362.78,1857.22 1464.23,1857.22 1502.84,1818.61 1617.43,1818.61 1674.54,1761.5 1767.43,1761.5 1959.34,1569.6 v1(1969.4,1569.6) v1(2175,1569.6) v1(2368,1569.6) 2433.26,1569.6 2639.21,1775.54 3034.43,1775.54 v1(3046.39,1787.5) 3058.39,1799.5 3093.74,1799.5 3132.24,1838 v1(3141,1838) 3141,1864 3147.5,1870.5 3147.5,1877.5 3144,1881 3140,1881 3139,1882 3139,1886.01 v1(3139.53,1886.53) 3140.17,1887.18 3140.17,1898.21 3145.96,1904 3152,1904 3153,1905 3153,1906.64 3154,1907.64 v1(3155.81,1907.64) ; v1(1375,255) v1(1330,255) v1(1290,255) v1(1255,255) 857.93,255 838.56,274.37 708.37,274.37 681.1,247.1 v1(681.1,226.18) 670,215.08 670,190 685,175 v1(711,175) v1(770,175) 950.85,175 951.31,174.54 v1(965.33,174.54) v1(991.98,174.54) v1(1096.89,174.54) v1(1124.26,174.54) v1(1153.26,174.54) 1420.44,174.54 1446.91,201 v1(1508,201) v1(1549,201) v1(1652,201) v1(1689,201) v1(1741,201) ; v1(1560.01,884.99) v1(1641.5,803.5) ; 1683.71,283.29 1683.71,284.71 1743.44,344.44 v1(1743.44,399.16) ; v1(1692,2411.47) 1692,2392 1727.57,2356.43 1727.57,2003.6 1931.5,1799.68 1985.3,1799.68 2068.55,1716.42 2205.72,1716.42 v1(2218.64,1729.34) v1(2373,1729.34) 2390.77,1729.34 2585,1923.58 v1(2585,1935) 2596.7,1923.3 2934.59,1923.3 2983.72,1972.43 3009.58,1972.43 3014.85,1977.7 3014.85,2031.7 3038.31,2055.15 v1(3038.31,2065.6) ; v1(3107,2822.35) 3113.83,2829.17 3160.17,2829.17 v1(3204.03,2873.03) v1(3224,2893) 3228.09,2897.09 v1(3325,2897.09) v1(3360,2897.09) v1(3395,2897.09) v1(3487,2897.09) v1(3522,2897.09) 3706.53,2897.09 3739.65,2930.2 3739.65,2931.2 3850.6,3042.16 3938,3042.16 3975.84,3080 v1(4225,3080) 4389,3080 4412,3057 v1(4412,3050) 4412,3028 4387.71,3003.71 4227.4,3003.71 4166.28,2942.59 v1(4040,2942.59) 3880.55,2942.59 3728.39,2790.43 v1(3624,2790.43) v1(3527,2790.43) 3508.43,2790.43 3498,2780 ; C363.1@3177.56,2410 3176.72,2410.84 3176.72,2446.72 3190.51,2460.51 v1(3190.51,2665.12) 3190.51,2667.66 3254.5,2731.65 v1(3254.5,2732.5) 3312,2790 v1(3368,2790) v1(3479,2790) 3488,2790 3498,2780 ; 3184.85,1997.14 3242.72,2055.01 C151.1@3242.72,2065.01 ; v1(3508.42,2270) 3515.25,2263.17 3515.25,2027.34 3507.87,2019.96 v1(3502.13,2019.96) 3469.96,2019.96 3373.73,1923.73 3373.73,1766.27 v1(3378.73,1761.27) 3378.73,1701.27 v1(3380,1700) 3379.33,1699.33 v1(3379.33,1642.81) v1(3379.33,1596.27) 3379.33,1590.36 v1(3411.16,1558.53) 3428.26,1541.44 3483.71,1541.44 v1(3500.8,1558.52) 3510.48,1558.52 3531.11,1579.15 3605.89,1579.15 3634.89,1608.15 3666.15,1608.15 3676.59,1618.59 3676.59,1671.48 3681.86,1676.76 3752.31,1676.76 3802,1627.07 3802,1607.65 3916.92,1492.73 3909.73,1492.73 v1(3907,1490) 3908.84,1490 3924,1474.84 J27.39@3971.02,1474.84 ; v1(3620,1810) 3652,1810 3670,1792 3670,1757.23 3689.48,1737.76 3776.76,1737.76 3790,1751 3846,1751 3846,1859.21 3803.02,1902.2 3757.2,1902.2 3724,1869 3724,1857 3722.76,1855.76 v1(3722.76,1844.49) ; v1(3620,1915.6) 3657.6,1915.6 3686,1944 3846.33,1944 v1(3860,1930.33) 3860,1905.7 3878,1887.7 3878,1779.18 3961.18,1696 4017.41,1696 4043.85,1669.56 4043.85,1613.85 v1(4022.95,1592.95) J27.51@3971.02,1592.95 ; v1(3625,2495) 3715,2495 3738.09,2471.91 3738.09,2372.57 3754.25,2356.4 3754.25,2154.4 3922.4,1986.25 3934.75,1986.25 v1(3935,1986) 3943.52,1994.52 4149.48,1994.52 4172,1972 4358,1972 v1(4360,1970) ; J27.57@3944.99,1652.01 J27.57@3971.02,1652.01 ; v1(4415,2024) 4251,2024 4225.83,2049.17 4179.17,2049.17 v1(4170,2040) v1(3960,2040) v1(3935,2040) 3918,2040 3792.5,2165.5 3792.5,2368.84 3776.34,2385 3776.34,2489.57 3498,2767.91 3498,2780
  BOTTOM w10: v1(697.84,2407.16) 680,2389.31 680,2155 v1(675,2150) 675,2135 653,2113 653,1974.66 677,1950.66 v1(677,1885.18) v1(677,1858.53) 677,1779 823,1633 ; v1(802.5,672.5) 817.85,687.85 984.8,687.85 1010.96,714 1062.88,714 1067.88,719 1482.07,719 v1(1490.6,727.53) 1499.13,719 1575,719 1603,747 v1(1603,765) v1(1641.5,803.5) ; 807.71,996.6 861.36,996.6 890,967.96 v1(890,957.83) 1142.31,957.83 1197.56,1013.07 v1(1197.56,1045) 1197.56,1060.36 1228.87,1091.67 v1(1293.34,1091.67) 1363.21,1091.67 v1(1386.69,1115.15) ; C158.1@1047.28,2365 1030,2365 1019.57,2375.43 v1(1019.57,2414.57) 1019.57,2514.57 1035,2530 1185,2530 1200,2515 1200,2427 1228,2399 1235,2399 v1(1239,2395) ; v1(1049,755.91) 1185.91,755.91 v1(1190,760) ; v1(1265,2660) 1265,2696 1185.17,2775.83 844.17,2775.83 J23.8@780,2840 780,2944 839,3003 1143.37,3003 1327,2819.37 1327,2770 1425,2672 v1(1425,2620) 1420,2615 v1(1420,2510) ; v1(1340,1790) v1(1439,1790) 1469.39,1759.61 1584.75,1759.61 1665.41,1678.94 1723.63,1678.94 1745,1657.57 v1(1745,1640) ; v1(1640,2760) 1554,2760 1490,2824 J22.10@1490,2940 1490,2950 1591,3051 v1(1630,3051) v1(1725,3051) 1781,3051 v1(1795,3065) 1806,3065 1836,3035 1946.97,3035 1989.97,2992 2049.82,2992 2123.31,2918.51 2123.31,2836.91 2195.22,2765 2305,2765 v1(2355,2715) ; v1(1675,2304) 1685,2294 v1(1685,2200) 1690.83,2194.17 1690.83,2043.11 v1(1687.72,2040) ; v1(1741,201) 1837.14,201 v1(1862.32,226.18) 1881.18,226.18 1928,273 v1(1928,322) 1928,362.64 v1(1866.64,424) ; 1823,2701 1869.27,2747.27 1916.27,2747.27 1924.6,2755.6 1982.8,2755.6 1994.99,2743.4 v1(1994.99,2625.6) 1996.19,2624.4 v1(1996.19,2534.4) 1988.4,2534.4 1978,2524 v1(1978,2508.78) ; v1(2718,2549) 2718,2592 2710,2600 2710,2710 2695.92,2724.08 2684.88,2724.08 v1(2642.28,2766.68) 2611.42,2735.83 2530.99,2735.83 2503.32,2763.5 2448.32,2763.5 2411.82,2800 2280,2800 2260,2820 J21.10@2260,2940 2385,3065 v1(2420,3065) v1(2500,3065) v1(2575,3065) 2679,3065 2855,2889 2884.49,2889 3080.48,2693.01 v1(3080.48,2633.19) 3080.48,2548.15 v1(3083.49,2545.14) ; 3846,1751 3925,1672 v1(3925,1660) 3932.99,1652.01 J27.57@3944.99,1652.01 ; v1(3907,1490) 3916.92,1480.08 3916.92,1437.08 3938.21,1415.79 J27.33@3971.02,1415.79 ; v1(3907.89,1239.36) 3908.63,1238.62 J27.15@3971.02,1238.62 ; 3921.27,1356.73 J27.27@3971.02,1356.73 ; 3925.68,1297.68 J27.21@3971.02,1297.68 ; J27.9@3971.02,1179.57 4010.57,1179.57 4020,1189 v1(4020,1224) ; J27.39@3971.02,1474.84 4009.2,1474.84 v1(4022.68,1488.33) ; J27.45@3971.02,1533.9 v1(4023.35,1533.9) ; v1(4119.14,880) 4137.32,880 4155.82,898.5 4317.82,898.5 4484.32,1065 v1(4500,1065) 4640,1065 v1(4640.43,1064.57) 4669.89,1064.57 4764.83,1159.51 4764.83,1238.17 v1(4740,1263) 4740,1271 4723,1288 4642.28,1288 v1(4617,1262.72) 4576.11,1221.83 4520.15,1221.83 4392.16,1093.84 4334.16,1093.84
  BOTTOM w12: C330.1@2062.28,2410 2062.28,2529.9 v1(2062.73,2530.35)
  BOTTOM w15: v1(205,1715) 205,1732.27 C82.1@225.01,1752.28 ; v1(1345,2577) v1(1345,2605) D80.2@1345,2643.15 ; C155.1@1527.28,2129.99 1527.28,2102.72 v1(1532.36,2097.64) ; R216.2@1562.72,2265 C338.1@1562.72,2225.01 v1(1589.99,2225.01) ; R211.2@1652.72,2305 1674,2305 v1(1675,2304) ; C128.1@1955,2337.72 1958.94,2337.72 1981.68,2314.98 v1(1981.68,2306.7) ; v1(2036.56,2741.05) v1(2036.56,2714.4) 2065,2685.96 D36.2@2065,2673.15 ; R179.1@2130,2037.28 2130,2020.98 v1(2140.98,2010) ; R180.1@2205,2037.28 2205,2013.91 v1(2201.69,2010.6) 2201.69,1998.31 2212.72,1987.28 C143.1@2212.72,1975.01 ; v1(2225,2625.6) D35.2@2225,2673.15 v1(2225,2714.4) ; v1(2245,2010.6) R181.1@2245,2037.28 ; v1(2320,2010) R184.1@2320,2037.28 ; v1(2410,2010) C328.1@2410,2037.28 ; XT2.4@2609.57,2297.24 2609.57,2318.23 v1(2630,2338.66) ; C318.1@3035,2092.28 3035,2077.76 3038.31,2074.45 v1(3038.31,2065.6) ; C151.1@3242.72,2065.01 3252.11,2065.01 3273.55,2086.45 3273.55,2093.26 v1(3292.17,2111.87)
  BOTTOM w20: 89.61,3491.9 J1.6@116.3,3491.9 ; 116.3,3435.69 J1.6@116.3,3491.9 ; 142.99,3491.9 J1.6@116.3,3491.9 ; 221.5,3208.4 J1.3@260,3208.4 ; 260,3142.34 J1.3@260,3208.4 ; 260,3274.46 J1.3@260,3208.4 ; 298.5,3208.4 J1.3@260,3208.4 ; 426.2,3208.4 J1.2@464.7,3208.4 ; 461.26,2254.85 J16.14@461.26,2287.44 ; 461.26,2320.03 J16.14@461.26,2287.44 ; 464.7,3142.34 J1.2@464.7,3208.4 ; 464.7,3274.46 J1.2@464.7,3208.4 ; 475.41,3491.9 J1.5@502.1,3491.9 ; 493.85,2287.44 J16.14@461.26,2287.44 ; 502.1,3435.69 J1.5@502.1,3491.9 ; 503.2,3208.4 J1.2@464.7,3208.4 ; 507.41,2287.44 J16.13@540,2287.44 ; 528.78,3491.9 J1.5@502.1,3491.9 ; 540,2254.85 J16.13@540,2287.44 ; 540,2320.03 J16.13@540,2287.44 ; 572.59,2287.44 J16.13@540,2287.44 ; 639.26,1465 J27.G4@744.68,1465 744.68,1570.43 ; 748,2840 J23.8@780,2840 ; 780,2808 J23.8@780,2840 ; 812,2840 J23.8@780,2840 ; v1(1019.57,2414.57) XT4.4@1057.76,2414.57 ; v1(1047.28,2342.28) C158.1@1047.28,2365 ; v1(1105.43,2485.43) XT4.2@1152.24,2485.43 ; C156.2@1162.72,2365 1209,2365 v1(1239,2395) ; R209.2@1230,2477.72 C341.1@1270,2477.72 v1(1270,2505) ; C340.1@1350,2042.28 1350,2004 v1(1358,1996) ; v1(1533.33,1957.6) 1559.88,1957.6 R187.1@1572.28,1970 ; C132.1@1687.72,2010 v1(1687.72,2040) ; v1(1834.57,2285.83) XT3.4@1834.57,2327.24 ; v1(1875.99,2410.39) 1876.38,2410 1910.6,2410 C332.1@1917.28,2410 R183.1@1917.28,2450 C334.1@1917.28,2490 ; XT3.2@1905.43,2232.76 1915.91,2222.28 C129.1@1955,2222.28 1975.8,2222.28 v1(1981.68,2216.41) ; v1(2006.96,2010.71) 2020,2023.75 C333.1@2020,2037.28 ; C331.1@2222.72,2410 v1(2222.72,2505) ; 2223,2940 J21.10@2260,2940 2260,2977 ; v1(2308.32,2350) 2315.6,2342.72 C364.1@2335,2342.72 ; XT2.2@2680.43,2202.76 2719.52,2202.76 v1(2725,2197.28) C116.2@2750,2197.28 ; v1(2721.67,2312.72) C115.2@2750,2312.72 ; C326.1@2845,2092.28 2845,2074.69 v1(2854.69,2065) ; C320.1@2917.72,1970 v1(2917.72,2000) ; C126.2@2917.72,2090 C321.1@2917.72,2130 v1(2917.72,2157.28) ; 3109.34,3020.12 J42.20@3171.34,3020.12 ; 3109.34,3243.74 J42.21@3171.34,3243.74 ; C325.1@3112.72,2330 v1(3143.98,2330) ; 3171.34,2958.12 J42.20@3171.34,3020.12 ; 3171.34,3082.12 J42.20@3171.34,3020.12 ; 3171.34,3181.74 J42.21@3171.34,3243.74 ; 3171.34,3305.74 J42.21@3171.34,3243.74 ; C363.1@3177.56,2410 3205,2410 3217.41,2422.41 v1(3217.41,2441.15) ; 3233.34,3020.12 J42.20@3171.34,3020.12 ; 3233.34,3243.74 J42.21@3171.34,3243.74 ; 3263.2,3039.02 J42.13@3292.2,3039.02 ; 3263.2,3165 J42.4@3292.2,3165 ; 3292.2,3068.02 J42.13@3292.2,3039.02 ; 3292.2,3194 J42.4@3292.2,3165 ; 3321.2,3039.02 J42.13@3292.2,3039.02 ; 3321.2,3165 J42.4@3292.2,3165 ; 3357.49,117.72 J54.4@3388.11,117.72 ; 3388.11,87.09 J54.4@3388.11,117.72 ; 3388.11,148.34 J54.4@3388.11,117.72 ; 3401,2979.96 J42.16@3430,2979.96 ; 3401,3105.94 J42.7@3430,3105.94 ; 3430,3008.96 J42.16@3430,2979.96 ; 3430,3076.94 J42.7@3430,3105.94 ; 3430,3134.94 J42.7@3430,3105.94 ; 3459,2979.96 J42.16@3430,2979.96 ; 3459,3105.94 J42.7@3430,3105.94 ; 3626.66,3243.74 J42.22@3688.66,3243.74 ; 3688.66,3305.74 J42.22@3688.66,3243.74 ; 3750.66,3243.74 J42.22@3688.66,3243.74 ; v1(4460.01,2270) C61.1@4460.01,2302.28 ; C314.1@4544.99,2322.72 4550,2327.73 4550,2385 v1(4551,2386) ; 4728.78,540 M6.1@4785,540 ; 4785,483.79 M6.1@4785,540 ; 4785,596.22 M6.1@4785,540 ; 5035.36,3430 SW4.2@5067.95,3430 ; 5067.95,3397.41 SW4.2@5067.95,3430 ; 5067.95,3462.59 SW4.2@5067.95,3430 ; 5096.38,3506.77 SW4.3@5128.98,3506.77 ; 5100.55,3430 SW4.2@5067.95,3430 ; 5128.98,3474.18 SW4.3@5128.98,3506.77 ; 5161.57,3506.77 SW4.3@5128.98,3506.77 ; 5176.66,1293.11 J56.4@5207.28,1293.11 ; 5205,2177.49 J8.4@5205,2208.11 5205,2238.73 ; 5207.28,1262.49 J56.4@5207.28,1293.11 ; 5207.28,1323.73 J56.4@5207.28,1293.11 ; 5237.91,1293.11 J56.4@5207.28,1293.11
